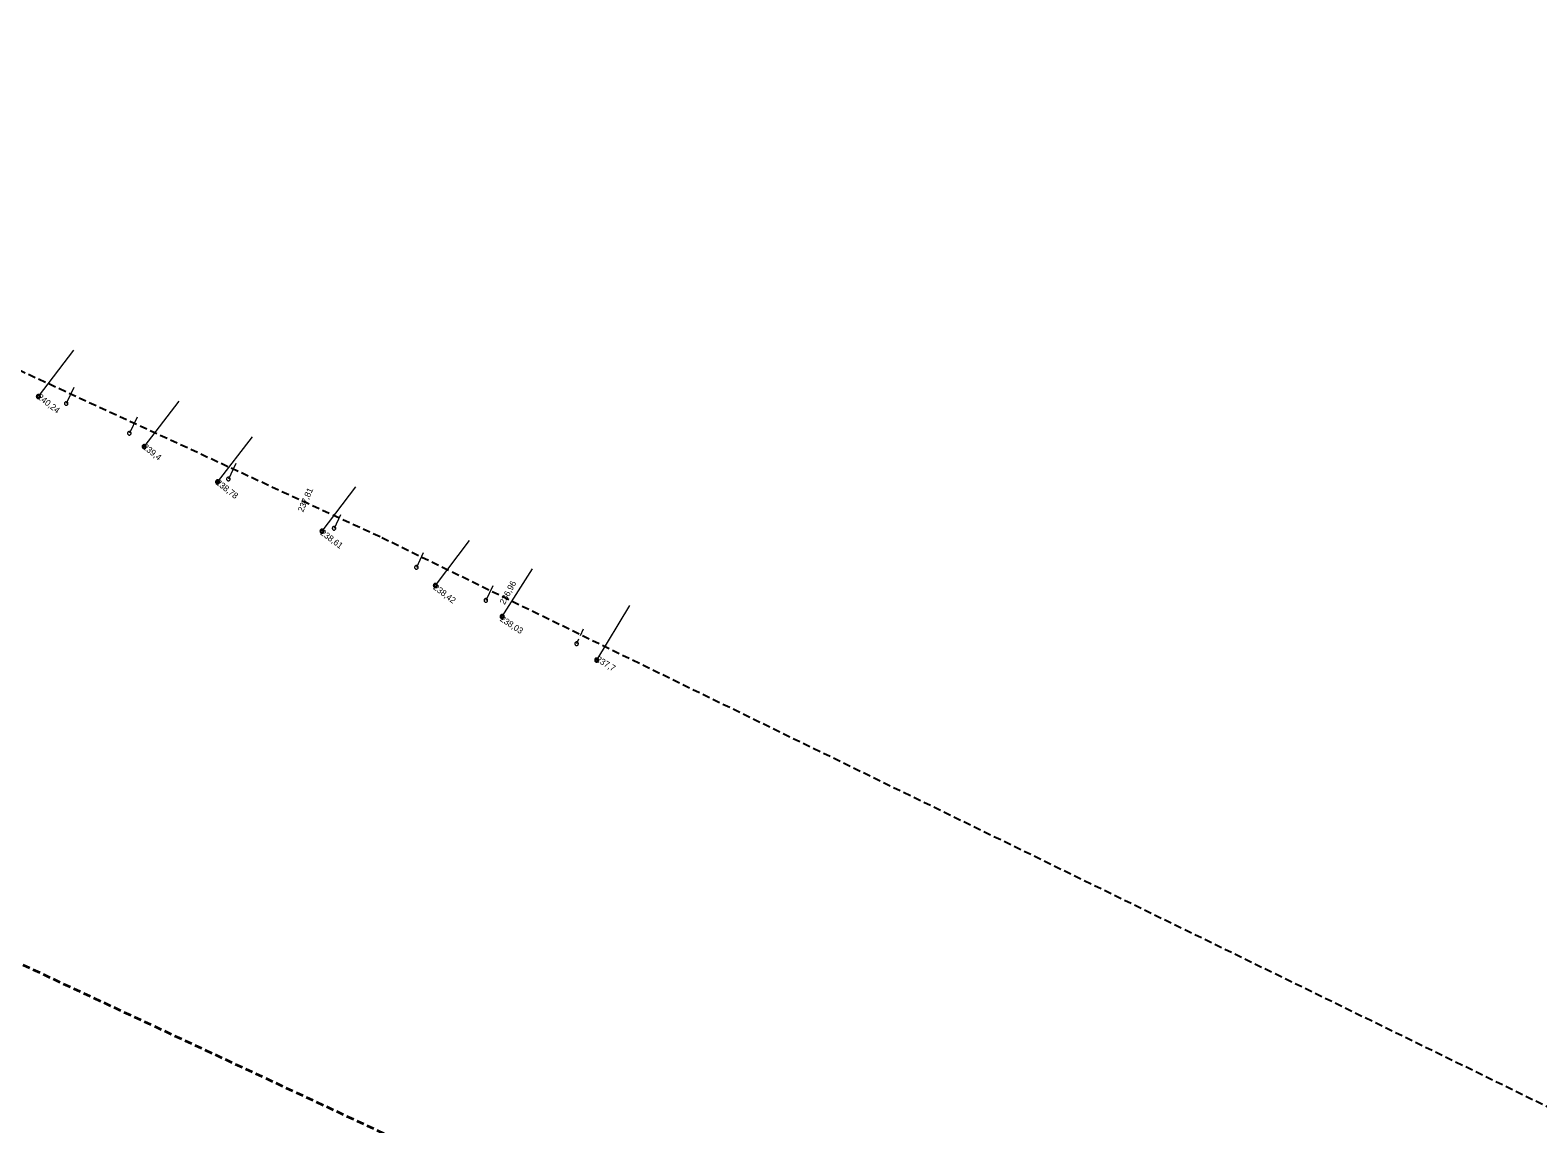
# Model space of a CAD drawing. Extents: x -735085 to -733500, y -1044153 to -1043402.
# Drawn here: x -734295.8 to -734101.4, y -1043837.5 to -1043696.6 of the extents above; entities that cross this region are included whole.
import ezdxf

# ---------------------------------------------------------------- set-up
doc = ezdxf.new("R2010")
doc.units = 0
doc.header["$LTSCALE"] = 0.32
doc.linetypes.add('MEDIUM_DASHED', pattern=[4.5, 3, -1.5])
doc.layers.add('16', color=7, linetype='Continuous')
for name, color, linetype, lineweight in [('18', 7, 'Continuous', 13), ('49', 7, 'Continuous', 13), ('63', 7, 'MEDIUM_DASHED', 25), ('8', 7, 'Continuous', 13)]:
    doc.layers.add(name, color=color, linetype=linetype, lineweight=lineweight)

msp = doc.modelspace()

# ---------------------------------------------------------------- linework, layer by layer
at = {"layer": '18'}
for points in [[(-734294.479, -1043743.768), (-734294.485, -1043743.712), (-734294.502, -1043743.659), (-734294.531, -1043743.61), (-734294.569, -1043743.569), (-734294.615, -1043743.537), (-734294.667, -1043743.515), (-734294.722, -1043743.504), (-734294.778, -1043743.506), (-734294.833, -1043743.519), (-734294.884, -1043743.544), (-734294.928, -1043743.579), (-734294.964, -1043743.622), (-734294.989, -1043743.672), (-734295.004, -1043743.727), (-734295.007, -1043743.783), (-734294.998, -1043743.838), (-734294.977, -1043743.891), (-734294.946, -1043743.937), (-734294.906, -1043743.976), (-734294.858, -1043744.006), (-734294.805, -1043744.025), (-734294.749, -1043744.032), (-734294.693, -1043744.028), (-734294.639, -1043744.011), (-734294.59, -1043743.984), (-734294.548, -1043743.946), (-734294.515, -1043743.901), (-734294.492, -1043743.85), (-734294.48, -1043743.795)], [(-734294.538, -1043743.771), (-734294.544, -1043743.722), (-734294.562, -1043743.676), (-734294.59, -1043743.635), (-734294.627, -1043743.602), (-734294.671, -1043743.58), (-734294.719, -1043743.568), (-734294.768, -1043743.568), (-734294.816, -1043743.58), (-734294.86, -1043743.603), (-734294.897, -1043743.636), (-734294.925, -1043743.677), (-734294.942, -1043743.724), (-734294.948, -1043743.773), (-734294.941, -1043743.822), (-734294.923, -1043743.868), (-734294.895, -1043743.908), (-734294.858, -1043743.941), (-734294.814, -1043743.963), (-734294.765, -1043743.975), (-734294.716, -1043743.974), (-734294.668, -1043743.962), (-734294.625, -1043743.938), (-734294.588, -1043743.905), (-734294.56, -1043743.864), (-734294.544, -1043743.817)], [(-734294.597, -1043743.775), (-734294.603, -1043743.733), (-734294.62, -1043743.695), (-734294.648, -1043743.664), (-734294.683, -1043743.641), (-734294.723, -1043743.63), (-734294.765, -1043743.63), (-734294.805, -1043743.642), (-734294.84, -1043743.665), (-734294.867, -1043743.697), (-734294.884, -1043743.735), (-734294.889, -1043743.776), (-734294.883, -1043743.818), (-734294.865, -1043743.855), (-734294.837, -1043743.887), (-734294.801, -1043743.909), (-734294.761, -1043743.92), (-734294.719, -1043743.919), (-734294.679, -1043743.906), (-734294.645, -1043743.883), (-734294.618, -1043743.85), (-734294.602, -1043743.812)], [(-734280.832, -1043750.231), (-734280.838, -1043750.175), (-734280.855, -1043750.122), (-734280.884, -1043750.073), (-734280.922, -1043750.032), (-734280.968, -1043750), (-734281.02, -1043749.978), (-734281.075, -1043749.967), (-734281.131, -1043749.969), (-734281.186, -1043749.982), (-734281.237, -1043750.007), (-734281.281, -1043750.042), (-734281.317, -1043750.085), (-734281.342, -1043750.135), (-734281.357, -1043750.19), (-734281.36, -1043750.246), (-734281.351, -1043750.301), (-734281.33, -1043750.354), (-734281.299, -1043750.4), (-734281.259, -1043750.439), (-734281.211, -1043750.469), (-734281.158, -1043750.488), (-734281.102, -1043750.495), (-734281.046, -1043750.491), (-734280.992, -1043750.474), (-734280.943, -1043750.447), (-734280.901, -1043750.409), (-734280.868, -1043750.364), (-734280.845, -1043750.313), (-734280.833, -1043750.258)], [(-734280.891, -1043750.234), (-734280.897, -1043750.185), (-734280.915, -1043750.139), (-734280.943, -1043750.098), (-734280.98, -1043750.065), (-734281.024, -1043750.043), (-734281.072, -1043750.031), (-734281.121, -1043750.031), (-734281.169, -1043750.043), (-734281.213, -1043750.066), (-734281.25, -1043750.099), (-734281.278, -1043750.14), (-734281.295, -1043750.187), (-734281.301, -1043750.236), (-734281.294, -1043750.285), (-734281.276, -1043750.331), (-734281.248, -1043750.371), (-734281.211, -1043750.404), (-734281.167, -1043750.426), (-734281.118, -1043750.438), (-734281.069, -1043750.437), (-734281.021, -1043750.425), (-734280.978, -1043750.401), (-734280.941, -1043750.368), (-734280.913, -1043750.327), (-734280.897, -1043750.28)], [(-734280.95, -1043750.238), (-734280.956, -1043750.196), (-734280.973, -1043750.158), (-734281.001, -1043750.127), (-734281.036, -1043750.104), (-734281.076, -1043750.093), (-734281.118, -1043750.093), (-734281.158, -1043750.105), (-734281.193, -1043750.128), (-734281.22, -1043750.16), (-734281.237, -1043750.198), (-734281.242, -1043750.239), (-734281.236, -1043750.281), (-734281.218, -1043750.318), (-734281.19, -1043750.35), (-734281.154, -1043750.372), (-734281.114, -1043750.383), (-734281.072, -1043750.382), (-734281.032, -1043750.369), (-734280.998, -1043750.346), (-734280.971, -1043750.313), (-734280.955, -1043750.275)], [(-734271.365, -1043754.774), (-734271.37, -1043754.718), (-734271.387, -1043754.665), (-734271.416, -1043754.616), (-734271.455, -1043754.575), (-734271.5, -1043754.543), (-734271.553, -1043754.521), (-734271.608, -1043754.51), (-734271.664, -1043754.512), (-734271.718, -1043754.525), (-734271.769, -1043754.55), (-734271.814, -1043754.585), (-734271.85, -1043754.628), (-734271.875, -1043754.678), (-734271.89, -1043754.733), (-734271.892, -1043754.789), (-734271.884, -1043754.844), (-734271.863, -1043754.897), (-734271.831, -1043754.943), (-734271.791, -1043754.982), (-734271.744, -1043755.012), (-734271.691, -1043755.031), (-734271.635, -1043755.038), (-734271.578, -1043755.034), (-734271.524, -1043755.017), (-734271.475, -1043754.99), (-734271.434, -1043754.952), (-734271.401, -1043754.907), (-734271.377, -1043754.856), (-734271.365, -1043754.801)], [(-734271.424, -1043754.777), (-734271.429, -1043754.728), (-734271.448, -1043754.682), (-734271.475, -1043754.641), (-734271.512, -1043754.608), (-734271.556, -1043754.586), (-734271.605, -1043754.574), (-734271.654, -1043754.574), (-734271.701, -1043754.586), (-734271.745, -1043754.609), (-734271.782, -1043754.642), (-734271.811, -1043754.683), (-734271.828, -1043754.73), (-734271.833, -1043754.779), (-734271.826, -1043754.828), (-734271.809, -1043754.874), (-734271.781, -1043754.914), (-734271.744, -1043754.947), (-734271.7, -1043754.969), (-734271.651, -1043754.981), (-734271.602, -1043754.98), (-734271.554, -1043754.968), (-734271.511, -1043754.944), (-734271.473, -1043754.911), (-734271.446, -1043754.87), (-734271.429, -1043754.823)], [(-734271.483, -1043754.781), (-734271.489, -1043754.739), (-734271.505, -1043754.701), (-734271.534, -1043754.67), (-734271.568, -1043754.647), (-734271.608, -1043754.636), (-734271.651, -1043754.636), (-734271.691, -1043754.648), (-734271.725, -1043754.671), (-734271.752, -1043754.703), (-734271.769, -1043754.741), (-734271.774, -1043754.782), (-734271.769, -1043754.824), (-734271.75, -1043754.861), (-734271.723, -1043754.893), (-734271.686, -1043754.915), (-734271.647, -1043754.926), (-734271.605, -1043754.925), (-734271.565, -1043754.912), (-734271.531, -1043754.889), (-734271.504, -1043754.856), (-734271.488, -1043754.818)], [(-734257.905, -1043761.128), (-734257.911, -1043761.072), (-734257.928, -1043761.019), (-734257.956, -1043760.97), (-734257.995, -1043760.929), (-734258.041, -1043760.897), (-734258.093, -1043760.875), (-734258.148, -1043760.864), (-734258.204, -1043760.866), (-734258.259, -1043760.879), (-734258.309, -1043760.904), (-734258.354, -1043760.939), (-734258.39, -1043760.982), (-734258.415, -1043761.032), (-734258.43, -1043761.087), (-734258.433, -1043761.143), (-734258.424, -1043761.198), (-734258.403, -1043761.251), (-734258.372, -1043761.297), (-734258.331, -1043761.336), (-734258.284, -1043761.366), (-734258.231, -1043761.385), (-734258.175, -1043761.392), (-734258.119, -1043761.388), (-734258.065, -1043761.371), (-734258.016, -1043761.344), (-734257.974, -1043761.306), (-734257.941, -1043761.261), (-734257.918, -1043761.21), (-734257.906, -1043761.155)], [(-734257.964, -1043761.131), (-734257.97, -1043761.082), (-734257.988, -1043761.036), (-734258.016, -1043760.995), (-734258.053, -1043760.962), (-734258.097, -1043760.94), (-734258.145, -1043760.928), (-734258.194, -1043760.928), (-734258.242, -1043760.94), (-734258.286, -1043760.963), (-734258.323, -1043760.996), (-734258.351, -1043761.037), (-734258.368, -1043761.084), (-734258.374, -1043761.133), (-734258.367, -1043761.182), (-734258.349, -1043761.228), (-734258.321, -1043761.268), (-734258.284, -1043761.301), (-734258.24, -1043761.323), (-734258.191, -1043761.335), (-734258.142, -1043761.334), (-734258.094, -1043761.322), (-734258.051, -1043761.298), (-734258.014, -1043761.265), (-734257.986, -1043761.224), (-734257.97, -1043761.177)], [(-734258.023, -1043761.135), (-734258.029, -1043761.093), (-734258.046, -1043761.055), (-734258.074, -1043761.024), (-734258.108, -1043761.001), (-734258.149, -1043760.99), (-734258.191, -1043760.99), (-734258.231, -1043761.002), (-734258.266, -1043761.025), (-734258.293, -1043761.057), (-734258.309, -1043761.095), (-734258.315, -1043761.136), (-734258.309, -1043761.178), (-734258.291, -1043761.215), (-734258.263, -1043761.247), (-734258.227, -1043761.269), (-734258.187, -1043761.28), (-734258.145, -1043761.279), (-734258.105, -1043761.266), (-734258.071, -1043761.243), (-734258.044, -1043761.21), (-734258.028, -1043761.172)], [(-734243.292, -1043768.123), (-734243.298, -1043768.067), (-734243.315, -1043768.014), (-734243.343, -1043767.965), (-734243.382, -1043767.924), (-734243.428, -1043767.892), (-734243.48, -1043767.87), (-734243.535, -1043767.859), (-734243.591, -1043767.861), (-734243.646, -1043767.874), (-734243.696, -1043767.899), (-734243.741, -1043767.934), (-734243.777, -1043767.977), (-734243.802, -1043768.027), (-734243.817, -1043768.082), (-734243.82, -1043768.138), (-734243.811, -1043768.193), (-734243.79, -1043768.246), (-734243.759, -1043768.292), (-734243.718, -1043768.331), (-734243.671, -1043768.361), (-734243.618, -1043768.38), (-734243.562, -1043768.387), (-734243.505, -1043768.383), (-734243.451, -1043768.366), (-734243.402, -1043768.339), (-734243.361, -1043768.301), (-734243.328, -1043768.256), (-734243.304, -1043768.205), (-734243.293, -1043768.15)], [(-734243.351, -1043768.126), (-734243.357, -1043768.077), (-734243.375, -1043768.031), (-734243.402, -1043767.99), (-734243.44, -1043767.957), (-734243.483, -1043767.935), (-734243.532, -1043767.923), (-734243.581, -1043767.923), (-734243.629, -1043767.935), (-734243.673, -1043767.958), (-734243.71, -1043767.991), (-734243.738, -1043768.032), (-734243.755, -1043768.079), (-734243.761, -1043768.128), (-734243.754, -1043768.177), (-734243.736, -1043768.223), (-734243.708, -1043768.263), (-734243.671, -1043768.296), (-734243.627, -1043768.318), (-734243.578, -1043768.33), (-734243.529, -1043768.329), (-734243.481, -1043768.317), (-734243.438, -1043768.293), (-734243.401, -1043768.26), (-734243.373, -1043768.219), (-734243.357, -1043768.172)], [(-734243.41, -1043768.13), (-734243.416, -1043768.088), (-734243.433, -1043768.05), (-734243.461, -1043768.019), (-734243.495, -1043767.996), (-734243.536, -1043767.985), (-734243.578, -1043767.985), (-734243.618, -1043767.997), (-734243.652, -1043768.02), (-734243.679, -1043768.052), (-734243.696, -1043768.09), (-734243.701, -1043768.131), (-734243.696, -1043768.173), (-734243.678, -1043768.21), (-734243.65, -1043768.242), (-734243.614, -1043768.264), (-734243.574, -1043768.275), (-734243.532, -1043768.274), (-734243.492, -1043768.261), (-734243.458, -1043768.238), (-734243.431, -1043768.205), (-734243.415, -1043768.167)], [(-734234.681, -1043772.117), (-734234.686, -1043772.061), (-734234.703, -1043772.008), (-734234.732, -1043771.959), (-734234.771, -1043771.918), (-734234.816, -1043771.886), (-734234.869, -1043771.864), (-734234.924, -1043771.853), (-734234.98, -1043771.855), (-734235.034, -1043771.868), (-734235.085, -1043771.893), (-734235.13, -1043771.928), (-734235.166, -1043771.971), (-734235.191, -1043772.021), (-734235.206, -1043772.076), (-734235.208, -1043772.132), (-734235.2, -1043772.187), (-734235.179, -1043772.24), (-734235.147, -1043772.286), (-734235.107, -1043772.325), (-734235.059, -1043772.355), (-734235.007, -1043772.374), (-734234.951, -1043772.381), (-734234.894, -1043772.377), (-734234.84, -1043772.36), (-734234.791, -1043772.333), (-734234.75, -1043772.295), (-734234.717, -1043772.25), (-734234.693, -1043772.199), (-734234.681, -1043772.144)], [(-734234.74, -1043772.12), (-734234.745, -1043772.071), (-734234.764, -1043772.025), (-734234.791, -1043771.984), (-734234.828, -1043771.951), (-734234.872, -1043771.929), (-734234.921, -1043771.917), (-734234.97, -1043771.917), (-734235.017, -1043771.929), (-734235.061, -1043771.952), (-734235.098, -1043771.985), (-734235.127, -1043772.026), (-734235.144, -1043772.073), (-734235.149, -1043772.122), (-734235.142, -1043772.171), (-734235.125, -1043772.217), (-734235.097, -1043772.257), (-734235.059, -1043772.29), (-734235.016, -1043772.312), (-734234.967, -1043772.324), (-734234.918, -1043772.323), (-734234.87, -1043772.311), (-734234.826, -1043772.287), (-734234.789, -1043772.254), (-734234.762, -1043772.213), (-734234.745, -1043772.166)], [(-734234.799, -1043772.124), (-734234.804, -1043772.082), (-734234.821, -1043772.044), (-734234.85, -1043772.013), (-734234.884, -1043771.99), (-734234.924, -1043771.979), (-734234.967, -1043771.979), (-734235.007, -1043771.991), (-734235.041, -1043772.014), (-734235.068, -1043772.046), (-734235.085, -1043772.084), (-734235.09, -1043772.125), (-734235.085, -1043772.167), (-734235.066, -1043772.204), (-734235.039, -1043772.236), (-734235.002, -1043772.258), (-734234.963, -1043772.269), (-734234.921, -1043772.268), (-734234.88, -1043772.255), (-734234.847, -1043772.232), (-734234.82, -1043772.199), (-734234.804, -1043772.161)], [(-734222.481, -1043777.736), (-734222.487, -1043777.68), (-734222.504, -1043777.627), (-734222.532, -1043777.578), (-734222.571, -1043777.537), (-734222.617, -1043777.505), (-734222.669, -1043777.483), (-734222.724, -1043777.472), (-734222.78, -1043777.474), (-734222.835, -1043777.487), (-734222.886, -1043777.512), (-734222.93, -1043777.547), (-734222.966, -1043777.59), (-734222.991, -1043777.64), (-734223.006, -1043777.695), (-734223.009, -1043777.751), (-734223, -1043777.806), (-734222.979, -1043777.859), (-734222.948, -1043777.905), (-734222.907, -1043777.944), (-734222.86, -1043777.974), (-734222.807, -1043777.993), (-734222.751, -1043778), (-734222.695, -1043777.996), (-734222.641, -1043777.979), (-734222.592, -1043777.952), (-734222.55, -1043777.914), (-734222.517, -1043777.869), (-734222.494, -1043777.818), (-734222.482, -1043777.763)], [(-734222.54, -1043777.739), (-734222.546, -1043777.69), (-734222.564, -1043777.644), (-734222.592, -1043777.603), (-734222.629, -1043777.57), (-734222.673, -1043777.548), (-734222.721, -1043777.536), (-734222.77, -1043777.536), (-734222.818, -1043777.548), (-734222.862, -1043777.571), (-734222.899, -1043777.604), (-734222.927, -1043777.645), (-734222.944, -1043777.692), (-734222.95, -1043777.741), (-734222.943, -1043777.79), (-734222.925, -1043777.836), (-734222.897, -1043777.876), (-734222.86, -1043777.909), (-734222.816, -1043777.931), (-734222.767, -1043777.943), (-734222.718, -1043777.942), (-734222.67, -1043777.93), (-734222.627, -1043777.906), (-734222.59, -1043777.873), (-734222.562, -1043777.832), (-734222.546, -1043777.785)], [(-734222.599, -1043777.743), (-734222.605, -1043777.701), (-734222.622, -1043777.663), (-734222.65, -1043777.632), (-734222.684, -1043777.609), (-734222.725, -1043777.598), (-734222.767, -1043777.598), (-734222.807, -1043777.61), (-734222.842, -1043777.633), (-734222.869, -1043777.665), (-734222.886, -1043777.703), (-734222.891, -1043777.744), (-734222.885, -1043777.786), (-734222.867, -1043777.823), (-734222.839, -1043777.855), (-734222.803, -1043777.877), (-734222.763, -1043777.888), (-734222.721, -1043777.887), (-734222.681, -1043777.874), (-734222.647, -1043777.851), (-734222.62, -1043777.818), (-734222.604, -1043777.78)]]:
    msp.add_lwpolyline(points, close=True, dxfattribs=at)
at = {"layer": '49'}
for p, q in [((-734294.743, -1043743.781), (-734290.16, -1043737.781)), ((-734294.743, -1043743.781), (-734290.16, -1043737.781)), ((-734281.096, -1043750.244), (-734276.578, -1043744.379)), ((-734281.096, -1043750.244), (-734276.578, -1043744.379)), ((-734271.629, -1043754.787), (-734267.134, -1043748.967)), ((-734271.629, -1043754.787), (-734267.134, -1043748.967)), ((-734258.169, -1043761.141), (-734253.807, -1043755.403)), ((-734258.169, -1043761.141), (-734253.807, -1043755.403)), ((-734243.556, -1043768.136), (-734239.153, -1043762.307)), ((-734243.556, -1043768.136), (-734239.153, -1043762.307)), ((-734234.945, -1043772.13), (-734231.019, -1043765.97)), ((-734234.945, -1043772.13), (-734231.019, -1043765.97)), ((-734222.745, -1043777.749), (-734218.482, -1043770.701)), ((-734222.745, -1043777.749), (-734218.482, -1043770.701))]:
    msp.add_line(p, q, dxfattribs=at)
at = {"layer": '63'}
msp.add_lwpolyline([(-734957.565, -1043435.501), (-734250.468, -1043761.931), (-734250.468, -1043761.931), (-733815.986, -1043973.969)], dxfattribs=at)
at = {"layer": '8'}
for p, q in [((-734290.18, -1043742.6), (-734291.144, -1043744.665)), ((-734282.02, -1043746.43), (-734283.002, -1043748.514)), ((-734269.3, -1043752.41), (-734270.234, -1043754.41)), ((-734255.8, -1043759.02), (-734256.609, -1043760.765)), ((-734245.109, -1043763.91), (-734245.997, -1043765.798)), ((-734236.149, -1043768.16), (-734237.032, -1043770.046))]:
    msp.add_line(p, q, dxfattribs=at)
at = {"layer": '8', "linetype": 'MEDIUM_DASHED'}
msp.add_line((-734224.515, -1043773.742), (-734225.336, -1043775.634), dxfattribs=at)
at = {"layer": '8', "linetype": 'MEDIUM_DASHED', "lineweight": 35}
msp.add_lwpolyline([(-734536.445, -1043703.656), (-734437.539, -1043750.071), (-734375.002, -1043779.659), (-734325.456, -1043803.606), (-734187.217, -1043868.148)], dxfattribs=at)
at = {"layer": '8'}
for points in [[(-734291.055, -1043744.451), (-734291.104, -1043744.434), (-734291.157, -1043744.429), (-734291.209, -1043744.436), (-734291.259, -1043744.455), (-734291.302, -1043744.484), (-734291.338, -1043744.522), (-734291.365, -1043744.567), (-734291.38, -1043744.617), (-734291.384, -1043744.67), (-734291.376, -1043744.722), (-734291.355, -1043744.771), (-734291.325, -1043744.813), (-734291.286, -1043744.849), (-734291.24, -1043744.873), (-734291.189, -1043744.888), (-734291.137, -1043744.89), (-734291.085, -1043744.881), (-734291.037, -1043744.859), (-734290.995, -1043744.828), (-734290.961, -1043744.788), (-734290.937, -1043744.741), (-734290.924, -1043744.69), (-734290.924, -1043744.637), (-734290.935, -1043744.586), (-734290.957, -1043744.539), (-734290.989, -1043744.497), (-734291.03, -1043744.465)], [(-734282.913, -1043748.3), (-734282.963, -1043748.283), (-734283.015, -1043748.278), (-734283.067, -1043748.285), (-734283.117, -1043748.304), (-734283.16, -1043748.333), (-734283.196, -1043748.371), (-734283.223, -1043748.416), (-734283.238, -1043748.466), (-734283.242, -1043748.519), (-734283.234, -1043748.571), (-734283.213, -1043748.62), (-734283.183, -1043748.662), (-734283.144, -1043748.698), (-734283.098, -1043748.722), (-734283.047, -1043748.737), (-734282.995, -1043748.739), (-734282.943, -1043748.73), (-734282.895, -1043748.708), (-734282.853, -1043748.677), (-734282.819, -1043748.637), (-734282.795, -1043748.59), (-734282.782, -1043748.539), (-734282.782, -1043748.486), (-734282.793, -1043748.435), (-734282.815, -1043748.388), (-734282.847, -1043748.346), (-734282.888, -1043748.314)], [(-734270.145, -1043754.196), (-734270.195, -1043754.179), (-734270.248, -1043754.174), (-734270.3, -1043754.181), (-734270.349, -1043754.2), (-734270.393, -1043754.229), (-734270.428, -1043754.268), (-734270.455, -1043754.313), (-734270.471, -1043754.363), (-734270.474, -1043754.415), (-734270.465, -1043754.468), (-734270.445, -1043754.516), (-734270.415, -1043754.559), (-734270.375, -1043754.594), (-734270.329, -1043754.619), (-734270.279, -1043754.633), (-734270.227, -1043754.635), (-734270.175, -1043754.626), (-734270.126, -1043754.604), (-734270.085, -1043754.573), (-734270.051, -1043754.532), (-734270.027, -1043754.486), (-734270.014, -1043754.435), (-734270.014, -1043754.382), (-734270.025, -1043754.33), (-734270.047, -1043754.283), (-734270.08, -1043754.242), (-734270.121, -1043754.209)], [(-734256.52, -1043760.551), (-734256.57, -1043760.534), (-734256.623, -1043760.529), (-734256.675, -1043760.536), (-734256.724, -1043760.555), (-734256.768, -1043760.584), (-734256.803, -1043760.623), (-734256.83, -1043760.668), (-734256.846, -1043760.718), (-734256.849, -1043760.77), (-734256.84, -1043760.823), (-734256.82, -1043760.871), (-734256.79, -1043760.914), (-734256.75, -1043760.949), (-734256.704, -1043760.974), (-734256.654, -1043760.988), (-734256.601, -1043760.99), (-734256.55, -1043760.981), (-734256.501, -1043760.959), (-734256.46, -1043760.928), (-734256.426, -1043760.887), (-734256.402, -1043760.841), (-734256.389, -1043760.79), (-734256.389, -1043760.737), (-734256.4, -1043760.685), (-734256.422, -1043760.638), (-734256.455, -1043760.597), (-734256.496, -1043760.564)], [(-734245.908, -1043765.584), (-734245.957, -1043765.567), (-734246.01, -1043765.562), (-734246.062, -1043765.569), (-734246.112, -1043765.588), (-734246.155, -1043765.617), (-734246.191, -1043765.655), (-734246.218, -1043765.7), (-734246.233, -1043765.75), (-734246.237, -1043765.803), (-734246.229, -1043765.855), (-734246.208, -1043765.904), (-734246.178, -1043765.946), (-734246.139, -1043765.982), (-734246.093, -1043766.006), (-734246.042, -1043766.021), (-734245.99, -1043766.023), (-734245.938, -1043766.014), (-734245.89, -1043765.992), (-734245.848, -1043765.961), (-734245.814, -1043765.921), (-734245.79, -1043765.875), (-734245.777, -1043765.823), (-734245.777, -1043765.77), (-734245.788, -1043765.719), (-734245.81, -1043765.672), (-734245.842, -1043765.63), (-734245.883, -1043765.598)], [(-734236.942, -1043769.832), (-734236.992, -1043769.815), (-734237.045, -1043769.81), (-734237.097, -1043769.817), (-734237.146, -1043769.835), (-734237.19, -1043769.865), (-734237.226, -1043769.903), (-734237.252, -1043769.948), (-734237.268, -1043769.998), (-734237.272, -1043770.05), (-734237.264, -1043770.103), (-734237.243, -1043770.151), (-734237.214, -1043770.194), (-734237.174, -1043770.229), (-734237.128, -1043770.254), (-734237.078, -1043770.269), (-734237.025, -1043770.271), (-734236.974, -1043770.262), (-734236.925, -1043770.241), (-734236.884, -1043770.209), (-734236.849, -1043770.169), (-734236.825, -1043770.123), (-734236.812, -1043770.072), (-734236.812, -1043770.019), (-734236.823, -1043769.967), (-734236.845, -1043769.92), (-734236.877, -1043769.878), (-734236.918, -1043769.846)], [(-734225.248, -1043775.42), (-734225.297, -1043775.403), (-734225.35, -1043775.398), (-734225.402, -1043775.405), (-734225.451, -1043775.424), (-734225.495, -1043775.453), (-734225.53, -1043775.492), (-734225.557, -1043775.537), (-734225.573, -1043775.587), (-734225.576, -1043775.64), (-734225.567, -1043775.692), (-734225.547, -1043775.74), (-734225.517, -1043775.783), (-734225.477, -1043775.818), (-734225.431, -1043775.843), (-734225.381, -1043775.857), (-734225.328, -1043775.859), (-734225.277, -1043775.85), (-734225.228, -1043775.828), (-734225.187, -1043775.796), (-734225.153, -1043775.756), (-734225.129, -1043775.71), (-734225.116, -1043775.658), (-734225.116, -1043775.606), (-734225.127, -1043775.554), (-734225.149, -1043775.507), (-734225.182, -1043775.466), (-734225.223, -1043775.433)]]:
    msp.add_lwpolyline(points, close=True, dxfattribs=at)

# ---------------------------------------------------------------- texts
at = {"layer": '16'}
for s, rotation, p in [('240,24', 322, (-734294.939, -1043743.982)), ('239,4 ', 322, (-734281.368, -1043750.414)), ('238,78', 322, (-734271.95, -1043755.008)), ('237,81', 66, (-734260.617, -1043758.739)), ('238,61', 323, (-734258.466, -1043761.478)), ('238,42', 323, (-734243.911, -1043768.53)), ('236,96', 62, (-734234.628, -1043770.671)), ('238,03', 327, (-734235.309, -1043772.631)), ('237,7 ', 329, (-734222.92, -1043777.847))]:
    msp.add_text(s, height=0.8, rotation=rotation, dxfattribs=at).set_placement(p)

doc.saveas('drawing.dxf')
